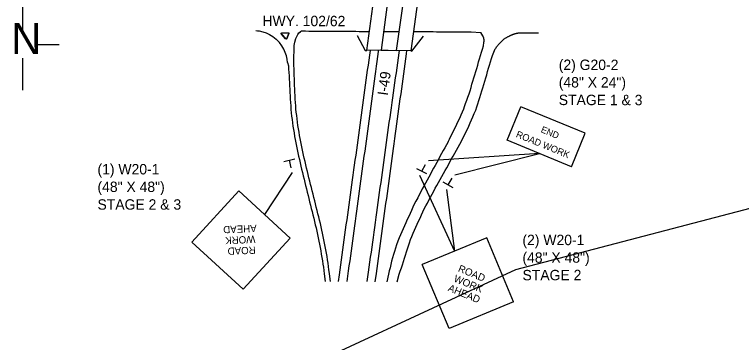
# Model space of a CAD drawing. Extents: x 1017892 to 1236694, y 658811 to 792468.
# Drawn here: x 1023347 to 1024427, y 659657 to 660145 of the extents above; entities that cross this region are included whole.
import ezdxf

# ---------------------------------------------------------------- set-up
doc = ezdxf.new("R2010")
doc.units = 0
for name, color, linetype in [('Level 3', 7, 'Continuous'), ('Level 42', 7, 'Continuous'), ('Level 8', 7, 'Continuous'), ('R_Border', 7, 'Continuous'), ('R_Draft', 7, 'Continuous'), ('R_Proposed Road Annot', 7, 'Continuous'), ('S_BRIDGE', 7, 'Continuous'), ('S_CURB', 7, 'Continuous'), ('S_EDGE_PAVEMENT', 7, 'Continuous'), ('S_MISC_STRUCTURES', 7, 'Continuous'), ('S_SIDEWALK', 7, 'Continuous')]:
    doc.layers.add(name, color=color, linetype=linetype)

msp = doc.modelspace()

# ---------------------------------------------------------------- linework, layer by layer
at = {"layer": 'Level 3'}
for p, q in [((1023746.8, 659926.3), (1023763.2, 659930.2)), ((1023755, 659928), (1023757.6, 659916.8)), ((1023952.2, 659911.8), (1023957.5, 659922)), ((1023959.5, 659907.7), (1023944.6, 659915.5)), ((1023991.4, 659891.5), (1023997.1, 659901.5)), ((1023998.6, 659887.1), (1023983.9, 659895.4))]:
    msp.add_line(p, q, dxfattribs=at)
at = {"layer": 'Level 8'}
for p, q in [((1024079, 659957.8), (1024099.4, 660007.6)), ((1024195.2, 659968.2), (1024099.4, 660007.6)), ((1024174.8, 659918.5), (1024195.2, 659968.2)), ((1024174.8, 659918.5), (1024079, 659957.8)), ((1023610.1, 659806.1), (1023680.2, 659882.4)), ((1023680.2, 659882.4), (1023756.6, 659812.3)), ((1023610.1, 659806.1), (1023686.5, 659736)), ((1023686.5, 659736), (1023756.6, 659812.3)), ((1024048.6, 659812.8), (1023952.9, 659773)), ((1024088.5, 659717.1), (1024048.6, 659812.8)), ((1023992.8, 659677.3), (1023952.9, 659773)), ((1024088.5, 659717.1), (1023992.8, 659677.3))]:
    msp.add_line(p, q, dxfattribs=at)
at = {"layer": 'R_Border'}
msp.add_lwpolyline([(1023703.1, 659584.8), (1024091.7, 659765.6), (1025330.1, 660089.9)], dxfattribs=at)
at = {"layer": 'R_Draft'}
for p, q in [((1023359.2, 660119.7), (1023359.2, 660282.4)), ((1023379.8, 660100.6), (1023412.8, 660100.6)), ((1023359.2, 660032.5), (1023359.2, 660080.3))]:
    msp.add_line(p, q, dxfattribs=at)
at = {"layer": 'R_Proposed Road Annot'}
for p, q in [((1024126.9, 659938.2), (1023961.9, 659927.4)), ((1024001, 659906.3), (1024126.9, 659938.2)), ((1023759.3, 659909.7), (1023718.4, 659847.3)), ((1023948.8, 659905.8), (1024000.8, 659792.9)), ((1023988.8, 659884.5), (1024000.8, 659792.9))]:
    msp.add_line(p, q, dxfattribs=at)
at = {"layer": 'S_BRIDGE'}
for points in [[(1023870.3, 660091.6), (1023882.3, 660179.5), (1023903.2, 660179.4), (1023891.6, 660092), (1023870.3, 660091.6)], [(1023914.6, 660091.4), (1023926.7, 660179), (1023947.7, 660178.6), (1023935.9, 660091.1), (1023914.6, 660091.4)]]:
    msp.add_lwpolyline(points, dxfattribs=at)
at = {"layer": 'S_CURB'}
msp.add_lwpolyline([(1023754.6, 660116.7), (1023751.7, 660109.3), (1023751.6, 660109.2), (1023751.5, 660109.1), (1023751.4, 660109), (1023751.3, 660108.9), (1023751.3, 660108.8), (1023751.2, 660108.8), (1023751.1, 660108.7), (1023751.1, 660108.7), (1023751, 660108.7), (1023750.9, 660108.7), (1023750.8, 660108.6), (1023750.8, 660108.6), (1023750.7, 660108.6), (1023750.6, 660108.6), (1023750.5, 660108.6), (1023750.4, 660108.6), (1023750.4, 660108.6), (1023750.3, 660108.6), (1023750.2, 660108.7), (1023750.1, 660108.7), (1023750, 660108.7), (1023749.9, 660108.8), (1023749.8, 660108.9), (1023749.7, 660109), (1023743.5, 660116.1), (1023743.4, 660116.2), (1023743.3, 660116.2), (1023743.3, 660116.3), (1023743.3, 660116.4), (1023743.2, 660116.5), (1023743.2, 660116.5), (1023743.2, 660116.6), (1023743.2, 660116.7), (1023743.2, 660116.8), (1023743.2, 660116.8), (1023743.2, 660116.9), (1023743.2, 660117), (1023743.2, 660117.1), (1023743.3, 660117.2), (1023743.3, 660117.3), (1023743.4, 660117.4), (1023743.4, 660117.4), (1023743.5, 660117.5), (1023743.5, 660117.5), (1023743.6, 660117.6), (1023743.7, 660117.6), (1023743.7, 660117.7), (1023743.8, 660117.7), (1023743.9, 660117.8), (1023743.9, 660117.8), (1023744, 660117.8), (1023744.1, 660117.8), (1023744.2, 660117.8), (1023753.7, 660118.1), (1023753.8, 660118.1), (1023753.9, 660118.1), (1023754, 660118), (1023754.1, 660118), (1023754.2, 660117.9), (1023754.4, 660117.9), (1023754.5, 660117.8), (1023754.5, 660117.7), (1023754.6, 660117.5), (1023754.7, 660117.4), (1023754.7, 660117.3), (1023754.7, 660117.2), (1023754.7, 660117), (1023754.7, 660116.9), (1023754.7, 660116.8)], close=True, dxfattribs=at)
for points in [[(1023743.8, 660116.1), (1023743.8, 660116.2), (1023743.7, 660116.3), (1023743.7, 660116.4), (1023743.7, 660116.6), (1023743.6, 660116.7), (1023743.7, 660116.8), (1023743.7, 660116.9), (1023743.7, 660117), (1023743.8, 660117.1), (1023743.8, 660117.2), (1023743.9, 660117.3), (1023744, 660117.3), (1023744.1, 660117.4), (1023744.2, 660117.4), (1023744.3, 660117.5), (1023744.4, 660117.5)], [(1023744.4, 660117.5), (1023753.5, 660117.9)], [(1023751.5, 660109.6), (1023754.3, 660116.7)], [(1023753.5, 660117.9), (1023753.6, 660117.9), (1023753.7, 660117.8), (1023753.8, 660117.8), (1023753.9, 660117.8), (1023754, 660117.7), (1023754, 660117.7), (1023754.1, 660117.6), (1023754.2, 660117.5), (1023754.3, 660117.4), (1023754.3, 660117.3), (1023754.3, 660117.2), (1023754.3, 660117.1), (1023754.3, 660117), (1023754.3, 660116.9), (1023754.3, 660116.8), (1023754.3, 660116.7)], [(1023749.8, 660109.3), (1023743.8, 660116.1)], [(1023749.8, 660109.3), (1023749.9, 660109.2), (1023750, 660109.2), (1023750.1, 660109.1), (1023750.2, 660109), (1023750.3, 660109), (1023750.4, 660109), (1023750.6, 660109), (1023750.7, 660109), (1023750.9, 660109), (1023751, 660109.1), (1023751.1, 660109.1), (1023751.2, 660109.2), (1023751.3, 660109.3), (1023751.4, 660109.4), (1023751.4, 660109.5), (1023751.5, 660109.6)]]:
    msp.add_lwpolyline(points, dxfattribs=at)
at = {"layer": 'S_EDGE_PAVEMENT'}
for points in [[(1023705.6, 660121.1), (1023708.1, 660120.9)], [(1023708.6, 660120.8), (1023710.4, 660120.6)], [(1023710.4, 660120.6), (1023715.6, 660119.5)], [(1023715.6, 660119.5), (1023720.6, 660117.8), (1023725.6, 660115.5), (1023730.6, 660112.4), (1023735.6, 660108.6), (1023740.5, 660103.4)], [(1023767.2, 660114.3), (1023767.8, 660115.6), (1023769.5, 660117.8), (1023771.6, 660119.5)], [(1023771.6, 660119.5), (1023771.8, 660119.6), (1023771.9, 660119.7), (1023772, 660119.8), (1023772.1, 660120), (1023772.3, 660120.1), (1023772.4, 660120.1), (1023772.6, 660120.2), (1023772.7, 660120.3), (1023772.9, 660120.4), (1023773.5, 660120.6)], [(1023773.5, 660120.6), (1023779, 660120.6), (1023784, 660120.5), (1023789, 660120.5), (1023794, 660120.5), (1023799, 660120.4), (1023804, 660120.4), (1023809, 660120.4), (1023814, 660120.3), (1023819, 660120.3), (1023824, 660120.3), (1023829, 660120.2), (1023834, 660120.2), (1023839, 660120.2), (1023844, 660120.1), (1023849, 660120.1), (1023854, 660120.1), (1023859, 660120), (1023864, 660120), (1023869, 660120), (1023874.2, 660120)], [(1023895.3, 660119.9), (1023899, 660119.8), (1023905.9, 660119.8), (1023910.6, 660119.8), (1023915.3, 660119.8), (1023918.6, 660119.7)], [(1023939.8, 660119.7), (1023954, 660119.6), (1023959, 660119.6), (1023964, 660119.6), (1023969, 660119.6), (1023974, 660119.5), (1023979, 660119.5), (1023984, 660119.5), (1023989, 660119.4), (1023994, 660119.3), (1023999, 660119.3), (1024004, 660119.3), (1024009, 660119.2), (1024014, 660119.2), (1024019, 660119.2), (1024020.4, 660119.2), (1024025.5, 660119.2), (1024039.9, 660118.6)], [(1024044.3, 660103.5), (1024044.4, 660103.9), (1024044.5, 660104.2), (1024044.5, 660104.6), (1024044.6, 660104.9), (1024044.6, 660105.3), (1024044.6, 660105.7), (1024044.6, 660106), (1024044.6, 660106.4), (1024044.6, 660106.7), (1024044.6, 660107.1), (1024044.6, 660107.5), (1024044.6, 660107.8), (1024044.5, 660108.2), (1024044.5, 660108.6), (1024044.4, 660108.9), (1024044.4, 660109.3), (1024044.3, 660109.6), (1024044.2, 660110), (1024044.1, 660110.3), (1024044, 660110.7), (1024043.9, 660111), (1024043.8, 660111.4), (1024043.6, 660111.7), (1024043.5, 660112.1), (1024043.4, 660112.4), (1024043.2, 660112.7), (1024043.1, 660113), (1024042.9, 660113.4), (1024039.9, 660118.6)], [(1024082.6, 660113.3), (1024083, 660113.6), (1024083.5, 660113.8), (1024084, 660114), (1024084.5, 660114.3), (1024085, 660114.5), (1024085.5, 660114.7), (1024085.9, 660114.9), (1024086.4, 660115.1), (1024086.9, 660115.3), (1024087.4, 660115.5), (1024087.9, 660115.7), (1024088.4, 660115.8), (1024088.9, 660116), (1024089.4, 660116.2), (1024089.9, 660116.3), (1024090.4, 660116.5)], [(1024090.4, 660116.5), (1024091, 660116.7), (1024091.7, 660116.9), (1024092.3, 660117), (1024092.9, 660117.2), (1024093.5, 660117.3), (1024094.1, 660117.5), (1024094.8, 660117.6), (1024095.4, 660117.7), (1024096, 660117.8), (1024096.6, 660117.9), (1024097.3, 660117.9), (1024097.9, 660118), (1024098.6, 660118), (1024099.2, 660118.1), (1024099.8, 660118.1), (1024100.5, 660118.1)], [(1024100.5, 660118.1), (1024105.5, 660118.1), (1024110.5, 660118.1), (1024115.5, 660118.1), (1024120.5, 660118.1), (1024125.5, 660118.1)], [(1023770.4, 659965.2), (1023769.6, 659969.9), (1023768.7, 659974.8), (1023768, 659979.8), (1023767.3, 659984.7), (1023766.7, 659989.7), (1023766.1, 659994.7), (1023765.5, 659999.6), (1023765.1, 660004.3), (1023764.7, 660009.3), (1023764.3, 660014.3), (1023764, 660019.3), (1023763.8, 660024.3), (1023763.5, 660029.3), (1023763.3, 660034.3), (1023763.1, 660039.3), (1023762.9, 660044.2), (1023762.8, 660049.2), (1023762.6, 660054.2), (1023762.4, 660059.2), (1023762.3, 660064.2), (1023762.1, 660069.2), (1023762, 660074.2), (1023762, 660079.2), (1023762.1, 660084.2), (1023762.3, 660089.2), (1023762.4, 660094.2), (1023762.6, 660099.2), (1023763.3, 660104.2), (1023765.1, 660109.3), (1023767.2, 660114.3)], [(1024067.4, 660102.1), (1024067.9, 660102.6), (1024068.4, 660103.1), (1024069, 660103.7), (1024069.5, 660104.2), (1024070, 660104.7), (1024070.6, 660105.1), (1024071.2, 660105.6), (1024071.7, 660106.1)], [(1024071.7, 660106.1), (1024072.3, 660106.6), (1024072.9, 660107.2), (1024073.5, 660107.7), (1024074.2, 660108.2), (1024074.8, 660108.7), (1024075.5, 660109.2), (1024076.1, 660109.7), (1024076.8, 660110.2), (1024077.5, 660110.6), (1024078.2, 660111.1), (1024078.9, 660111.5), (1024079.6, 660111.9), (1024080.4, 660112.3), (1024081.1, 660112.6), (1024081.8, 660113), (1024082.6, 660113.3)], [(1023752.7, 660073.8), (1023751.9, 660078.8), (1023750.8, 660083.8), (1023749.1, 660088.8), (1023746.9, 660093.7), (1023744, 660098.6), (1023740.5, 660103.4)], [(1023991.2, 659955.6), (1023993.1, 659959.5), (1023995.3, 659964), (1023997.6, 659968.5), (1023999.9, 659972.9), (1024002.2, 659977.4), (1024004.3, 659981.9), (1024006.4, 659986.4), (1024008.5, 659990.9), (1024010.7, 659995.5), (1024012.6, 660000.1), (1024014.4, 660004.5), (1024015.7, 660008), (1024017.3, 660012.7), (1024019, 660017.4), (1024020.7, 660022.1), (1024022.3, 660026.9), (1024023.8, 660031.7), (1024025.3, 660036.4), (1024026.7, 660041.2), (1024028.2, 660046), (1024029.6, 660050.7), (1024031, 660055.4), (1024032.4, 660060.1), (1024033.8, 660064.9), (1024035.2, 660069.7), (1024036.6, 660074.5), (1024038.1, 660079.3), (1024039.5, 660084.1), (1024040.9, 660088.9), (1024042.3, 660093.7), (1024043.8, 660098.5), (1024044.3, 660103.5)], [(1024061.1, 660093.5), (1024061.9, 660094.6), (1024062.6, 660095.7), (1024063.4, 660096.8), (1024064.1, 660097.9), (1024064.9, 660098.9), (1024065.8, 660100), (1024066.6, 660101), (1024067.4, 660102.1)], [(1023828.5, 659747.5), (1023829.8, 659757.6), (1023830.8, 659765), (1023831.8, 659772.4), (1023832.8, 659779.9), (1023833.8, 659787.3), (1023834.9, 659794.7), (1023835.9, 659802.1), (1023836.9, 659809.6), (1023837.9, 659817), (1023838.9, 659824.4), (1023839.9, 659831.9), (1023841, 659839.3), (1023842, 659846.7), (1023843, 659854.1), (1023844, 659861.6), (1023845, 659869), (1023846.1, 659876.4), (1023847.1, 659883.9), (1023848.1, 659891.3), (1023849.1, 659898.7), (1023850.2, 659906.1), (1023851.2, 659913.6), (1023852.2, 659921), (1023853.2, 659928.4), (1023854.3, 659935.9), (1023855.3, 659943.3), (1023856.3, 659950.7), (1023857.3, 659958.1), (1023858.3, 659965.6), (1023859.4, 659973), (1023860.4, 659980.4), (1023861.4, 659987.8), (1023862.4, 659995.3), (1023863.4, 660002.7), (1023864.5, 660010.1), (1023865.5, 660017.5), (1023866.5, 660025), (1023867.5, 660032.4), (1023868.5, 660039.8), (1023869.6, 660047.3), (1023870.6, 660054.7), (1023871.6, 660062.1), (1023872.7, 660069.5), (1023873.7, 660077), (1023874.8, 660084.4), (1023875.7, 660091.7)], [(1023887.3, 660091.7), (1023887.1, 660090.3), (1023886.1, 660082.8), (1023885.2, 660075.4), (1023884.2, 660068), (1023883.2, 660060.5), (1023882.2, 660053.1), (1023881.2, 660045.7), (1023880.2, 660038.2), (1023879.2, 660030.8), (1023878.2, 660023.4), (1023877.2, 660015.9), (1023876.2, 660008.5), (1023875.2, 660001.1), (1023874.2, 659993.7), (1023873.2, 659986.2), (1023872.2, 659978.8), (1023871.2, 659971.4), (1023870.2, 659963.9), (1023869.2, 659956.5), (1023868.2, 659949.1), (1023867.2, 659941.6), (1023866.1, 659934.2), (1023865.1, 659926.8), (1023864.1, 659919.4), (1023863.1, 659911.9), (1023862.1, 659904.5), (1023861.1, 659897.1), (1023860, 659889.6), (1023859, 659882.2), (1023858, 659874.8), (1023857, 659867.4), (1023856, 659859.9), (1023855, 659852.5), (1023854, 659845.1), (1023852.9, 659837.6), (1023851.9, 659830.2), (1023850.9, 659822.8), (1023849.9, 659815.4), (1023848.9, 659807.9), (1023847.9, 659800.5), (1023846.9, 659793.1), (1023845.9, 659785.6), (1023844.9, 659778.2), (1023843.8, 659770.8), (1023842.8, 659763.4), (1023840.7, 659747.4)], [(1023918.4, 660091.4), (1023917.9, 660088.1), (1023916.9, 660080.7), (1023915.9, 660073.3), (1023914.8, 660065.8), (1023913.8, 660058.4), (1023912.7, 660051), (1023911.7, 660043.6), (1023910.7, 660036.1), (1023909.6, 660028.7), (1023908.6, 660021.3), (1023907.5, 660013.9), (1023906.5, 660006.4), (1023905.4, 659999), (1023904.4, 659991.6), (1023903.3, 659984.2), (1023902.3, 659976.7), (1023901.3, 659969.3), (1023900.2, 659961.9), (1023899.2, 659954.4), (1023898.2, 659947), (1023897.1, 659939.6), (1023896.1, 659932.2), (1023895.1, 659924.7), (1023894.1, 659917.3), (1023893, 659909.9), (1023892, 659902.5), (1023891, 659895), (1023889.9, 659887.6), (1023888.9, 659880.2), (1023887.9, 659872.8), (1023886.9, 659865.3), (1023885.8, 659857.9), (1023884.8, 659850.5), (1023883.8, 659843.1), (1023882.7, 659835.6), (1023881.7, 659828.2), (1023880.7, 659820.8), (1023879.6, 659813.3), (1023878.6, 659805.9), (1023877.6, 659798.5), (1023876.6, 659791.1), (1023875.5, 659783.6), (1023874.5, 659776.2), (1023873.5, 659768.8), (1023872.4, 659761.4), (1023870.5, 659747.3)], [(1023883, 659747.2), (1023884.6, 659759.7), (1023885.6, 659767.1), (1023886.6, 659774.5), (1023887.6, 659782), (1023888.6, 659789.4), (1023889.7, 659796.8), (1023890.7, 659804.3), (1023891.7, 659811.7), (1023892.7, 659819.1), (1023893.7, 659826.6), (1023894.7, 659834), (1023895.8, 659841.4), (1023896.8, 659848.8), (1023897.8, 659856.3), (1023898.8, 659863.7), (1023899.9, 659871.1), (1023900.9, 659878.5), (1023901.9, 659886), (1023902.9, 659893.4), (1023903.9, 659900.8), (1023904.9, 659908.3), (1023905.9, 659915.7), (1023907, 659923.1), (1023908, 659930.5), (1023909, 659938), (1023910, 659945.4), (1023911, 659952.8), (1023912, 659960.3), (1023913, 659967.7), (1023914, 659975.1), (1023915.1, 659982.5), (1023916.1, 659990), (1023917.1, 659997.4), (1023918.1, 660004.8), (1023919.1, 660012.3), (1023920.2, 660019.7), (1023921.2, 660027.1), (1023922.2, 660034.5), (1023923.2, 660042), (1023924.2, 660049.4), (1023925.3, 660056.8), (1023926.3, 660064.2), (1023927.3, 660071.7), (1023928.3, 660079.1), (1023929.3, 660086.5), (1023929.9, 660091.4)], [(1024006.1, 659947.5), (1024008.7, 659952.2), (1024010.9, 659956.7), (1024013.2, 659961.2), (1024015.4, 659965.6), (1024017.7, 659970.1), (1024019.9, 659974.6), (1024022.1, 659979.1), (1024024.2, 659983.6), (1024026.2, 659988.2), (1024028.2, 659992.8), (1024030.2, 659997.5), (1024032.3, 660002.8), (1024033.9, 660007.6), (1024035.5, 660012.3), (1024037.1, 660017), (1024038.5, 660021.8), (1024040, 660026.6), (1024041.5, 660031.4), (1024042.9, 660036.2), (1024044.3, 660041), (1024045.7, 660045.8), (1024047.2, 660050.7), (1024048.6, 660055.5), (1024050, 660060.3), (1024051.3, 660065.1), (1024052.7, 660069.9), (1024054, 660074.7), (1024055.5, 660079.5), (1024057.1, 660084.3), (1024059, 660088.9)], [(1024059, 660088.9), (1024059.2, 660089.5), (1024059.5, 660090.1), (1024059.7, 660090.7), (1024060, 660091.2), (1024060.2, 660091.8), (1024060.5, 660092.4), (1024060.8, 660092.9), (1024061.1, 660093.5)], [(1023752.7, 660073.8), (1023753.8, 660068.9), (1023754.2, 660063.9), (1023754.5, 660058.9), (1023754.9, 660053.9), (1023755.1, 660048.9), (1023755.3, 660043.9), (1023755.5, 660038.9), (1023755.7, 660033.9), (1023755.9, 660028.9), (1023756.2, 660023.9), (1023756.5, 660018.9), (1023756.8, 660013.9), (1023757.2, 660008.9), (1023757.6, 660003.9), (1023758.1, 659998.7), (1023758.6, 659993.7), (1023759.3, 659988.7), (1023759.9, 659983.7), (1023760.6, 659978.8), (1023761.4, 659973.8), (1023762.2, 659968.9), (1023763.1, 659963.7)], [(1023816.3, 659747.6), (1023815.5, 659754.8), (1023814.8, 659759.7), (1023814.1, 659764.8), (1023813.5, 659769.9), (1023812.7, 659774.8), (1023811.9, 659779.8), (1023811.2, 659784.7), (1023810.3, 659789.6), (1023809.4, 659794.5), (1023808.5, 659799.5), (1023807.5, 659804.5), (1023806.6, 659809.5), (1023805.6, 659814.4), (1023804.5, 659819.3), (1023803.5, 659824.2), (1023802.4, 659829.1), (1023801.3, 659834), (1023800.1, 659838.8), (1023798.9, 659843.7), (1023797.7, 659848.5), (1023796.5, 659853.4), (1023795.3, 659858.2), (1023794.1, 659863.1), (1023792.9, 659867.9), (1023791.6, 659872.8), (1023790.4, 659877.6), (1023789.2, 659882.5), (1023788, 659887.3), (1023786.8, 659892.2), (1023785.6, 659897), (1023784.4, 659901.9), (1023783.2, 659906.7), (1023782, 659911.6), (1023780.8, 659916.5), (1023779.7, 659921.3), (1023778.5, 659926.2), (1023777.4, 659931.1), (1023776.3, 659935.8), (1023775.3, 659940.7), (1023774.2, 659945.6), (1023773.2, 659950.5), (1023772.2, 659955.4), (1023771.3, 659960.3), (1023770.4, 659965.2)], [(1023763.1, 659963.7), (1023764, 659958.8), (1023765, 659953.9), (1023765.9, 659949), (1023766.9, 659944.1), (1023768, 659939.2), (1023769, 659934.3), (1023770.1, 659929.3), (1023771.2, 659924.4), (1023772.4, 659919.5), (1023773.5, 659914.7), (1023774.7, 659909.8), (1023775.8, 659905), (1023777, 659900.1), (1023778.2, 659895.2), (1023779.4, 659890.4), (1023780.6, 659885.5), (1023781.8, 659880.7), (1023783, 659875.8), (1023784.2, 659871), (1023785.4, 659866.1), (1023786.7, 659861.3), (1023787.9, 659856.4), (1023789.1, 659851.6), (1023790.2, 659846.7), (1023791.4, 659841.9), (1023792.6, 659837), (1023793.8, 659832.1), (1023794.9, 659827.3), (1023796, 659822.4), (1023797.1, 659817.5), (1023798.1, 659812.6), (1023799.1, 659807.7), (1023800, 659803), (1023800.9, 659798.2), (1023801.8, 659793.3), (1023802.7, 659788.4), (1023803.5, 659783.5), (1023804.4, 659778.5), (1023805.2, 659773.6), (1023805.9, 659768.7), (1023806.6, 659763.9), (1023807.2, 659759.1), (1023808.7, 659747.6)], [(1023991.2, 659955.6), (1023988.8, 659951.2), (1023986.4, 659946.8), (1023984, 659942.4), (1023981.6, 659938), (1023979.1, 659933.7), (1023976.7, 659929.3), (1023974.3, 659924.9), (1023971.9, 659920.5), (1023969.5, 659916.1), (1023967.2, 659911.7), (1023964.8, 659907.3), (1023962.4, 659902.9), (1023960, 659898.5), (1023957.7, 659894.1), (1023955.3, 659889.7), (1023952.9, 659885.3), (1023950.6, 659880.9), (1023948.3, 659876.5), (1023946, 659872), (1023943.4, 659867), (1023941, 659862.5), (1023938.7, 659858), (1023936.7, 659853.4), (1023934.7, 659848.9), (1023932.7, 659844.3), (1023930.6, 659839.7), (1023928.6, 659835.1), (1023926.6, 659830.6), (1023924.6, 659826), (1023922.5, 659821.4), (1023920.4, 659816.9), (1023918.3, 659812.4), (1023916.5, 659807.7), (1023914.5, 659802.1), (1023912.9, 659797.1), (1023911.3, 659792.3), (1023909.8, 659787.6), (1023908.5, 659782.7), (1023907.2, 659777.9), (1023906, 659773), (1023904.9, 659768.1), (1023903.8, 659763.2), (1023902.7, 659758.3), (1023900.1, 659747.1)], [(1023915.5, 659747), (1023918.7, 659758.3), (1023920.2, 659763.1), (1023921.7, 659767.8), (1023923.2, 659772.6), (1023924.7, 659777.4), (1023926.2, 659782.1), (1023927.7, 659786.9), (1023929.2, 659791.7), (1023930.7, 659796.3), (1023932.2, 659800.6), (1023933.9, 659805.3), (1023935.5, 659810), (1023937.4, 659814.6), (1023939.4, 659819.3), (1023941.4, 659823.9), (1023943.3, 659828.4), (1023945.3, 659833), (1023947.3, 659837.6), (1023949.5, 659842.1), (1023951.6, 659846.6), (1023953.7, 659851.2), (1023955.8, 659855.7), (1023958.2, 659860.1), (1023960.5, 659864.2), (1023962.8, 659868.6), (1023965.2, 659873.1), (1023967.5, 659877.5), (1023969.8, 659881.9), (1023972.2, 659886.3), (1023974.6, 659890.7), (1023977, 659895.1), (1023979.4, 659899.5), (1023981.8, 659903.9), (1023984.2, 659908.2), (1023986.7, 659912.6), (1023989.1, 659916.9), (1023991.6, 659921.3), (1023994, 659925.7), (1023996.4, 659930), (1023998.9, 659934.4), (1024001.3, 659938.8), (1024003.7, 659943.2), (1024006.1, 659947.5)]]:
    msp.add_lwpolyline(points, dxfattribs=at)
at = {"layer": 'S_MISC_STRUCTURES'}
msp.add_lwpolyline([(1023914.3, 660091.2), (1023902.3, 660091.5), (1023893.5, 660091.5), (1023891.7, 660091.6)], dxfattribs=at)
at = {"layer": 'S_SIDEWALK'}
for points in [[(1023855.9, 660113.8), (1023855.9, 660113.7), (1023868.1, 660091.7), (1023870.2, 660091.5)], [(1023935.6, 660091), (1023937.5, 660090.7), (1023954.6, 660112.9)]]:
    msp.add_lwpolyline(points, dxfattribs=at)

# ---------------------------------------------------------------- texts
at = {"layer": 'Level 3'}
msp.add_text('ROAD WORK', height=10.07, rotation=337.7004, dxfattribs=at).set_placement((1024091.2, 659963))
at = {"layer": 'Level 42'}
msp.add_text('END', height=9.76, rotation=337.7004, dxfattribs=at).set_placement((1024128.2, 659970.2))
at = {"layer": 'Level 8'}
for s, height, rotation, p in [('(2) G20-2', 15.5, 359.8778, (1024155.7, 660062.6)), ('(48" X 24")', 15.5, 359.8778, (1024155.7, 660036.5)), ('STAGE 1 & 3', 15.5, 359.8778, (1024155.7, 660010.3)), ('AHEAD', 10.8, 182.4315, (1023706.4, 659832.1)), ('WORK', 10.8, 182.4309, (1023704.5, 659815.8)), ('ROAD', 10.8, 182.4313, (1023704.9, 659799.7)), ('ROAD', 10.8, 337.6126, (1024005.1, 659762.8)), ('STAGE 2', 15.5, 0.0886, (1024101.8, 659749.3)), ('WORK', 10.8, 337.6122, (1023998.7, 659747.9)), ('AHEAD', 10.8, 337.6127, (1023990.1, 659733.9))]:
    msp.add_text(s, height=height, rotation=rotation, dxfattribs=at).set_placement(p)
for s, p in [('(1) W20-1', (1023470, 659907)), ('(48" X 48")', (1023470, 659880.8)), ('STAGE 2 & 3', (1023470, 659854.5)), ('(2) W20-1', (1024101.7, 659801.7)), ('(48" X 48")', (1024101.7, 659775.5))]:
    msp.add_text(s, height=15.5, dxfattribs=at).set_placement(p)
at = {"layer": 'R_Draft'}
msp.add_text('N', height=46.5, rotation=360, dxfattribs=at).set_placement((1023341.6, 660086.2))
at = {"layer": 'R_Proposed Road Annot'}
for s, rotation, p in [('HWY. 102/62', 359.8336, (1023715.2, 660128)), ('I-49', 82.4524, (1023901.5, 660023.8))]:
    msp.add_text(s, height=15.5, rotation=rotation, dxfattribs=at).set_placement(p)

doc.saveas('drawing.dxf')
